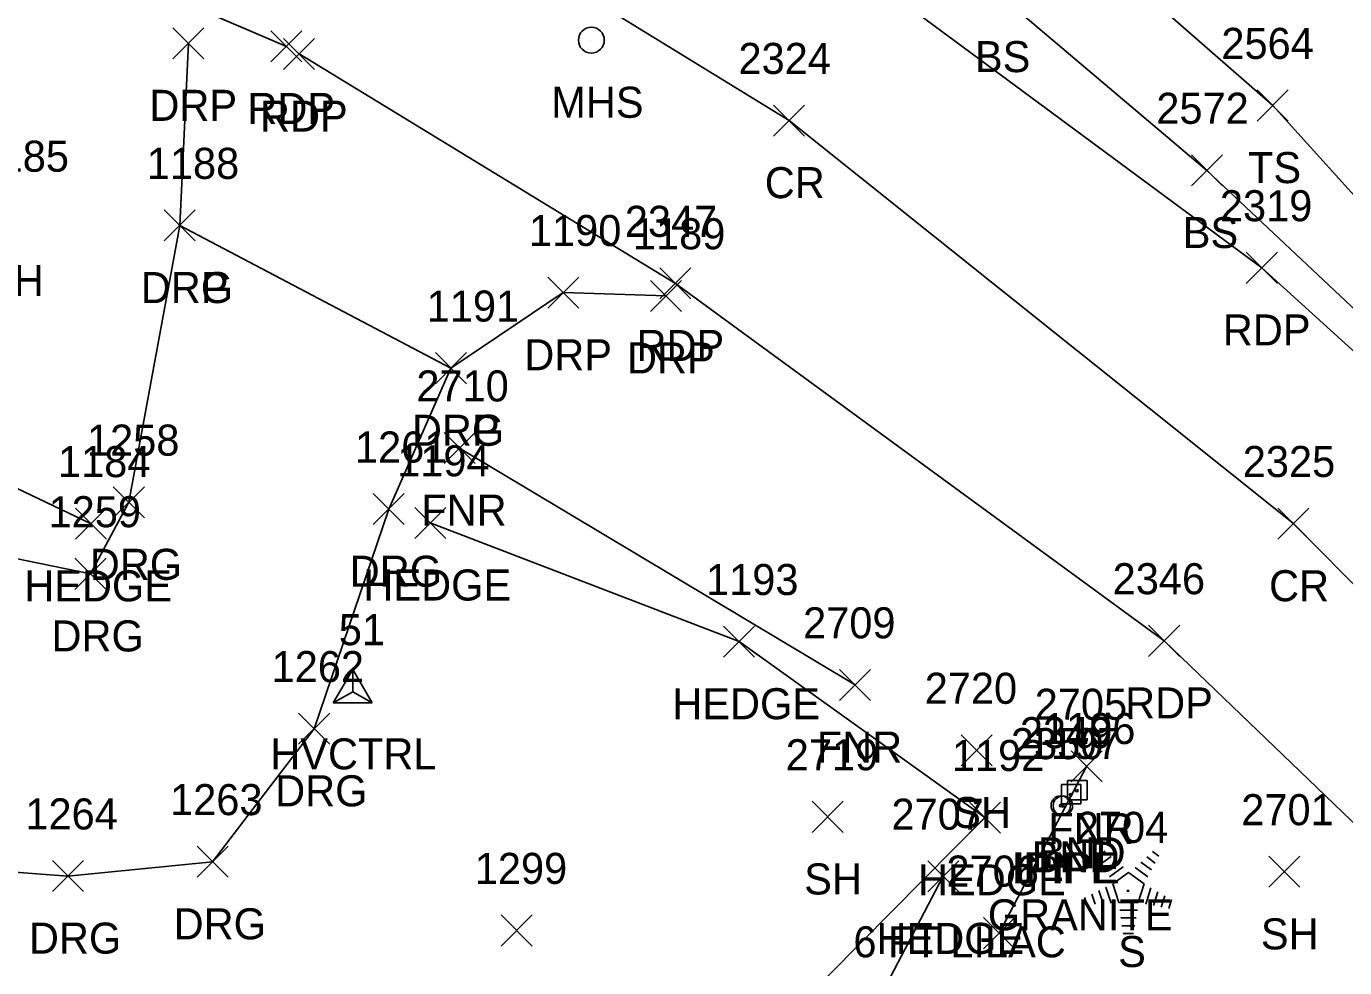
# Model space of a CAD drawing. Extents: x 1638344 to 1639591, y 610835 to 612202.
# Drawn here: x 1638794.9 to 1638879.7, y 611608.8 to 611669.4 of the extents above; entities that cross this region are included whole.
import ezdxf

# ---------------------------------------------------------------- set-up
doc = ezdxf.new("R2010")
doc.units = 0
for name, color, linetype in [('C_A', 7, 'Continuous'), ('C_I', 7, 'Continuous'), ('CPSM', 7, 'Continuous'), ('L_A', 7, 'Continuous'), ('L_C', 7, 'Continuous'), ('L_I', 7, 'Continuous'), ('L_TIC', 7, 'Continuous'), ('LAHR', 7, 'Continuous'), ('LELB', 7, 'Continuous'), ('Level 18', 7, 'Continuous'), ('LFNC', 7, 'Continuous'), ('LTC', 7, 'Continuous'), ('M_A', 7, 'Continuous'), ('M_C', 7, 'Continuous'), ('M_I', 7, 'Continuous'), ('MPIP', 7, 'Continuous'), ('P_A', 7, 'Continuous'), ('P_I', 7, 'Continuous'), ('P_TIC', 7, 'Continuous'), ('PET', 7, 'Continuous'), ('PRC', 7, 'Continuous'), ('R_A', 7, 'Continuous'), ('R_I', 7, 'Continuous'), ('R_TIC', 7, 'Continuous'), ('RDG', 7, 'Continuous'), ('RDP', 7, 'Continuous'), ('U_A', 7, 'Continuous'), ('USMH', 7, 'Continuous')]:
    doc.layers.add(name, color=color, linetype=linetype)

msp = doc.modelspace()

# ---------------------------------------------------------------- linework, layer by layer
at = {"layer": 'CPSM'}
for p, q in [((1638814.637, 611625.834), (1638815.887, 611627.999)), ((1638817.137, 611625.834), (1638815.887, 611627.999)), ((1638815.888, 611626.555), (1638815.887, 611627.999)), ((1638814.637, 611625.834), (1638815.888, 611626.555)), ((1638815.888, 611626.555), (1638815.888, 611626.555)), ((1638815.888, 611626.555), (1638817.137, 611625.834)), ((1638814.637, 611625.834), (1638817.137, 611625.834))]:
    msp.add_line(p, q, dxfattribs=at)
at = {"layer": 'L_TIC'}
for points in [[(1638874.108, 611663.315), (1638876.108, 611665.315)], [(1638876.108, 611663.315), (1638874.108, 611665.315)], [(1638869.873, 611659.135), (1638871.873, 611661.135)], [(1638871.873, 611659.135), (1638869.873, 611661.135)], [(1638821.762, 611641.254), (1638823.762, 611643.254)], [(1638823.762, 611641.254), (1638821.762, 611643.254)], [(1638798.04, 611636.379), (1638800.04, 611638.379)], [(1638800.04, 611636.379), (1638798.04, 611638.379)], [(1638819.874, 611636.431), (1638821.874, 611638.431)], [(1638821.874, 611636.431), (1638819.874, 611638.431)], [(1638839.755, 611628.784), (1638841.755, 611630.784)], [(1638841.755, 611628.784), (1638839.755, 611630.784)], [(1638847.222, 611625.995), (1638849.222, 611627.995)], [(1638849.222, 611625.995), (1638847.222, 611627.995)], [(1638855.05, 611621.779), (1638857.05, 611623.779)], [(1638857.05, 611621.779), (1638855.05, 611623.779)], [(1638862.123, 611620.749), (1638864.123, 611622.749)], [(1638864.123, 611620.749), (1638862.123, 611622.749)], [(1638845.46, 611617.498), (1638847.46, 611619.498)], [(1638847.46, 611617.498), (1638845.46, 611619.498)], [(1638855.577, 611617.45), (1638857.577, 611619.45)], [(1638857.577, 611617.45), (1638855.577, 611619.45)], [(1638855.577, 611617.45), (1638857.577, 611619.45)], [(1638857.577, 611617.45), (1638855.577, 611619.45)], [(1638874.853, 611613.961), (1638876.853, 611615.961)], [(1638876.853, 611613.961), (1638874.853, 611615.961)], [(1638852.901, 611613.669), (1638854.901, 611615.669)], [(1638854.901, 611613.669), (1638852.901, 611615.669)], [(1638825.443, 611610.179), (1638827.443, 611612.179)], [(1638827.443, 611610.179), (1638825.443, 611612.179)], [(1638856.497, 611610.005), (1638858.497, 611612.005)], [(1638858.497, 611610.005), (1638856.497, 611612.005)]]:
    msp.add_lwpolyline(points, dxfattribs=at)
at = {"layer": 'LAHR'}
for points in [[(1638761.697, 611652.078), (1638780.628, 611646.181), (1638799.04, 611637.379)], [(1638856.577, 611618.45), (1638840.755, 611629.784), (1638820.874, 611637.431)], [(1638856.577, 611618.45), (1638840.558, 611602.258), (1638827.804, 611576.732), (1638816.188, 611554.655), (1638804.751, 611532.583)], [(1638853.901, 611614.669), (1638842.923, 611593.705)]]:
    msp.add_lwpolyline(points, dxfattribs=at)
at = {"layer": 'LELB'}
for points in [[(1638873.205, 611711.87), (1638857.7, 611692.044), (1638852.155, 611680.328), (1638857.497, 611671.464), (1638870.873, 611660.135), (1638883.737, 611648.029), (1638891.391, 611642.842)], [(1638893.271, 611644.216), (1638875.108, 611664.315), (1638860.571, 611677.054), (1638859.029, 611684.692), (1638875.948, 611708.59)]]:
    msp.add_lwpolyline(points, dxfattribs=at)
at = {"layer": 'Level 18'}
for p, q in [((1638862.751, 611620.576), (1638861.501, 611620.576)), ((1638861.501, 611620.576), (1638861.501, 611619.326)), ((1638862.751, 611620.576), (1638861.501, 611620.576)), ((1638861.501, 611620.576), (1638861.501, 611619.326)), ((1638863.151, 611620.845), (1638861.901, 611620.845)), ((1638861.901, 611620.845), (1638861.901, 611619.595)), ((1638863.151, 611620.845), (1638861.901, 611620.845)), ((1638861.901, 611620.845), (1638861.901, 611619.595)), ((1638862.751, 611619.326), (1638862.751, 611620.576)), ((1638862.751, 611619.326), (1638862.751, 611620.576)), ((1638863.151, 611619.595), (1638863.151, 611620.845)), ((1638863.151, 611619.595), (1638863.151, 611620.845)), ((1638861.501, 611619.326), (1638862.751, 611619.326)), ((1638861.501, 611619.326), (1638862.751, 611619.326)), ((1638861.901, 611619.595), (1638863.151, 611619.595)), ((1638861.901, 611619.595), (1638863.151, 611619.595))]:
    msp.add_line(p, q, dxfattribs=at)
for centre in [(1638862.501, 611620.183), (1638862.101, 611619.914)]:
    msp.add_circle(centre, 0.0833, dxfattribs=at)
at = {"layer": 'LFNC'}
for points in [[(1638848.222, 611626.995), (1638822.762, 611642.254)], [(1638863.123, 611621.749), (1638857.497, 611611.005)]]:
    msp.add_lwpolyline(points, dxfattribs=at)
at = {"layer": 'LTC'}
for p, q in [((1638863.966, 611616.031), (1638864.321, 611616.289)), ((1638864.176, 611615.566), (1638864.705, 611615.95)), ((1638866.993, 611615.923), (1638867.543, 611615.524)), ((1638867.364, 611616.272), (1638867.784, 611615.967)), ((1638864.385, 611615.1), (1638865.089, 611615.611)), ((1638864.595, 611614.634), (1638865.473, 611615.272)), ((1638866.251, 611615.227), (1638867.061, 611614.638)), ((1638866.622, 611615.575), (1638867.302, 611615.081)), ((1638864.82, 611614.179), (1638865.831, 611614.914)), ((1638864.82, 611614.179), (1638865.207, 611612.986)), ((1638865.831, 611614.914), (1638866.828, 611614.189)), ((1638866.828, 611614.189), (1638866.437, 611612.986)), ((1638862.999, 611613.31), (1638863.151, 611612.842)), ((1638863.454, 611613.527), (1638863.666, 611612.875)), ((1638863.91, 611613.744), (1638864.181, 611612.908)), ((1638864.365, 611613.96), (1638864.696, 611612.941)), ((1638867.266, 611613.918), (1638866.928, 611612.878)), ((1638867.71, 611613.667), (1638867.423, 611612.783)), ((1638868.155, 611613.417), (1638867.918, 611612.688)), ((1638866.437, 611612.986), (1638865.207, 611612.986)), ((1638866.399, 611612.486), (1638865.254, 611612.486)), ((1638868.599, 611613.167), (1638868.412, 611612.593)), ((1638866.315, 611611.986), (1638865.327, 611611.986)), ((1638866.231, 611611.486), (1638865.4, 611611.486)), ((1638866.147, 611610.986), (1638865.472, 611610.986))]:
    msp.add_line(p, q, dxfattribs=at)
at = {"layer": 'MPIP'}
for centre, radius in [((1638861.462, 611619.223), 0.625), ((1638861.598, 611619.213), 0.625), ((1638861.462, 611619.223), 0.0833), ((1638861.598, 611619.213), 0.0833)]:
    msp.add_circle(centre, radius, dxfattribs=at)
at = {"layer": 'P_TIC'}
for points in [[(1638810.617, 611667.124), (1638812.617, 611669.124)], [(1638812.617, 611667.124), (1638810.617, 611669.124)], [(1638811.431, 611666.635), (1638813.431, 611668.635)], [(1638813.431, 611666.635), (1638811.431, 611668.635)], [(1638842.976, 611662.347), (1638844.976, 611664.347)], [(1638844.976, 611662.347), (1638842.976, 611664.347)], [(1638873.406, 611652.859), (1638875.406, 611654.859)], [(1638875.406, 611652.859), (1638873.406, 611654.859)], [(1638835.66, 611651.855), (1638837.66, 611653.855)], [(1638837.66, 611651.855), (1638835.66, 611653.855)], [(1638875.437, 611636.386), (1638877.437, 611638.386)], [(1638877.437, 611636.386), (1638875.437, 611638.386)], [(1638867.117, 611628.836), (1638869.117, 611630.836)], [(1638869.117, 611628.836), (1638867.117, 611630.836)]]:
    msp.add_lwpolyline(points, dxfattribs=at)
at = {"layer": 'PET'}
for points in [[(1638811.617, 611668.124), (1638782.382, 611680.66), (1638760.269, 611687.763), (1638749.075, 611690.276), (1638736.887, 611691.427), (1638737.261, 611703.383), (1638737.238, 611715.506), (1638749.613, 611712.202), (1638777.651, 611708.363), (1638798.655, 611701.427), (1638823.202, 611689.416)], [(1639148.644, 611331.084), (1639142.07, 611329.181), (1639135.695, 611328.741), (1639125.685, 611331.146), (1639119.176, 611334.876), (1639114.186, 611340.569), (1639098.763, 611361.782), (1639080.318, 611387.337), (1639061.62, 611413.479), (1639039.15, 611444.22), (1639014.337, 611480.362), (1638988.412, 611516.904), (1638963.389, 611551.848), (1638935.462, 611588.701), (1638918.51, 611609.364), (1638899.727, 611630.857), (1638874.406, 611653.859), (1638846.552, 611674.469), (1638833.143, 611682.537), (1638823.865, 611689.161)], [(1639117.365, 611283.377), (1639114.123, 611301.894), (1639095.515, 611328.502), (1639070.515, 611363.262), (1639041.381, 611404.693), (1639011.578, 611446.402), (1638984.33, 611485.148), (1638954.173, 611527.497), (1638934.327, 611554.774), (1638918.881, 611575.585), (1638893.271, 611605.667), (1638868.117, 611629.836), (1638836.66, 611652.855), (1638812.431, 611667.635)]]:
    msp.add_lwpolyline(points, dxfattribs=at)
at = {"layer": 'PRC'}
msp.add_lwpolyline([(1638818.793, 611678.836), (1638843.976, 611663.347), (1638876.437, 611637.386), (1638906.243, 611607.195), (1638934.14, 611573.691), (1638965.308, 611531.428), (1638998.822, 611484.341), (1639033.825, 611434.483), (1639068.011, 611386.3), (1639093.943, 611350.49), (1639111.892, 611325.375), (1639129.228, 611302.77)], dxfattribs=at)
at = {"layer": 'R_TIC'}
for points in [[(1638804.311, 611667.326), (1638806.311, 611669.326)], [(1638806.311, 611667.326), (1638804.311, 611669.326)], [(1638803.754, 611655.589), (1638805.754, 611657.589)], [(1638805.754, 611655.589), (1638803.754, 611657.589)], [(1638803.754, 611655.589), (1638805.754, 611657.589)], [(1638805.754, 611655.589), (1638803.754, 611657.589)], [(1638828.44, 611651.263), (1638830.44, 611653.263)], [(1638830.44, 611651.263), (1638828.44, 611653.263)], [(1638835.055, 611651.054), (1638837.055, 611653.054)], [(1638837.055, 611651.054), (1638835.055, 611653.054)], [(1638821.207, 611646.398), (1638823.207, 611648.398)], [(1638823.207, 611646.398), (1638821.207, 611648.398)], [(1638821.207, 611646.398), (1638823.207, 611648.398)], [(1638823.207, 611646.398), (1638821.207, 611648.398)], [(1638821.207, 611646.398), (1638823.207, 611648.398)], [(1638823.207, 611646.398), (1638821.207, 611648.398)], [(1638800.474, 611637.763), (1638802.474, 611639.763)], [(1638802.474, 611637.763), (1638800.474, 611639.763)], [(1638817.203, 611637.318), (1638819.203, 611639.318)], [(1638819.203, 611637.318), (1638817.203, 611639.318)], [(1638798.009, 611633.152), (1638800.009, 611635.152)], [(1638800.009, 611633.152), (1638798.009, 611635.152)], [(1638812.404, 611623.175), (1638814.404, 611625.175)], [(1638814.404, 611623.175), (1638812.404, 611625.175)], [(1638805.87, 611614.608), (1638807.87, 611616.608)], [(1638807.87, 611614.608), (1638805.87, 611616.608)], [(1638796.555, 611613.687), (1638798.555, 611615.687)], [(1638798.555, 611613.687), (1638796.555, 611615.687)]]:
    msp.add_lwpolyline(points, dxfattribs=at)
at = {"layer": 'RDG'}
for points in [[(1638804.754, 611656.589), (1638801.474, 611638.763), (1638799.009, 611634.152), (1638786.873, 611636.64), (1638769.768, 611642.842)], [(1638822.207, 611647.398), (1638818.203, 611638.318), (1638813.404, 611624.175), (1638806.87, 611615.608), (1638797.555, 611614.687), (1638788.459, 611615.375), (1638771.793, 611619.289), (1638763.161, 611621.314), (1638769.768, 611642.842)]]:
    msp.add_lwpolyline(points, dxfattribs=at)
at = {"layer": 'RDP'}
for points in [[(1638805.311, 611668.326), (1638804.754, 611656.589), (1638822.207, 611647.398)], [(1638836.055, 611652.054), (1638829.44, 611652.263), (1638822.207, 611647.398)]]:
    msp.add_lwpolyline(points, dxfattribs=at)
at = {"layer": 'USMH'}
for p, q in [((1638831.247, 611668.524), (1638831.247, 611668.524)), ((1638832.08, 611668.524), (1638832.08, 611668.524))]:
    msp.add_line(p, q, dxfattribs=at)
msp.add_circle((1638831.247, 611668.524), 0.833, dxfattribs=at)

# ---------------------------------------------------------------- texts
at = {"layer": 'C_A'}
msp.add_text('HVCTRL', height=2, dxfattribs=at).set_placement((1638810.58, 611621.555))
at = {"layer": 'C_I'}
msp.add_text('51', height=2, dxfattribs=at).set_placement((1638814.99, 611629.555))
at = {"layer": 'L_A'}
for s, p in [('BS', (1638855.938, 611666.464)), ('TS', (1638873.517, 611659.315)), ('BS', (1638869.314, 611655.135)), ('SH', (1638792.285, 611652.051)), ('FNR', (1638820.297, 611637.254)), ('HEDGE', (1638794.741, 611632.379)), ('HEDGE', (1638816.574, 611632.431)), ('HEDGE', (1638836.456, 611624.784)), ('FNR', (1638845.757, 611621.995)), ('SH', (1638854.538, 611617.779)), ('FNR', (1638860.658, 611616.749)), ('SH', (1638844.948, 611613.498)), ('HEDGE', (1638852.277, 611613.45)), ('HEDGE', (1638852.277, 611613.45)), ('HEDGE', (1638849.602, 611609.669)), ('SH', (1638874.341, 611609.961)), ('S', (1638865.157, 611608.823))]:
    msp.add_text(s, height=2, dxfattribs=at).set_placement(p)
at = {"layer": 'L_C'}
msp.add_text('6 FT LILAC', height=2, dxfattribs=at).set_placement((1638848.112, 611609.45))
msp.add_text('6 FT LILAC', height=2, dxfattribs=at).set_placement((1638848.112, 611609.45))
at = {"layer": 'L_I'}
for s, p in [('2564', (1638871.801, 611667.315)), ('2572', (1638867.613, 611663.135)), ('1185', (1638791.671, 611660.051)), ('2710', (1638819.982, 611645.254)), ('1184', (1638796.914, 611640.379)), ('1194', (1638818.748, 611640.431)), ('1193', (1638838.629, 611632.784)), ('2709', (1638844.876, 611629.995)), ('2720', (1638852.704, 611625.779)), ('2705', (1638859.784, 611624.749)), ('2719', (1638843.759, 611621.498)), ('1192', (1638854.451, 611621.45)), ('1192', (1638854.451, 611621.45)), ('2707', (1638850.562, 611617.669)), ('2701', (1638873.081, 611617.961)), ('2704', (1638862.432, 611616.823)), ('1299', (1638823.742, 611614.179)), ('2706', (1638854.103, 611614.005))]:
    msp.add_text(s, height=2, dxfattribs=at).set_placement(p)
at = {"layer": 'LTC'}
msp.add_text('.', height=1.037, rotation=270, dxfattribs=at).set_placement((1638865.714, 611613.927))
at = {"layer": 'M_A'}
for s, p in [('BND', (1638859.588, 611614.919)), ('BND', (1638859.988, 611615.188)), ('IPIPE', (1638858.297, 611614.223)), ('IPIPE', (1638858.433, 611614.213))]:
    msp.add_text(s, height=2, dxfattribs=at).set_placement(p)
at = {"layer": 'M_C'}
msp.add_text('GRANITE', height=2, dxfattribs=at).set_placement((1638856.768, 611611.188))
at = {"layer": 'M_I'}
for s, p in [('1196', (1638860.319, 611623.188)), ('2349', (1638858.832, 611622.919)), ('2350', (1638858.252, 611622.213)), ('1197', (1638859.336, 611622.223))]:
    msp.add_text(s, height=2, dxfattribs=at).set_placement(p)
at = {"layer": 'P_A'}
for s, p in [('RDP', (1638809.105, 611663.124)), ('RDP', (1638809.919, 611662.635)), ('CR', (1638842.409, 611658.347)), ('RDP', (1638871.894, 611648.859)), ('RDP', (1638834.148, 611647.855)), ('CR', (1638874.87, 611632.386)), ('RDP', (1638865.605, 611624.836))]:
    msp.add_text(s, height=2, dxfattribs=at).set_placement(p)
at = {"layer": 'P_I'}
for s, p in [('2324', (1638840.716, 611666.347)), ('2319', (1638871.705, 611656.859)), ('2347', (1638833.4, 611655.855)), ('2325', (1638873.177, 611640.386)), ('2346', (1638864.802, 611632.836))]:
    msp.add_text(s, height=2, dxfattribs=at).set_placement(p)
at = {"layer": 'R_A'}
for s, p in [('DRP', (1638802.799, 611663.326)), ('DRG', (1638802.243, 611651.589)), ('DRP', (1638802.243, 611651.589)), ('DRP', (1638826.928, 611647.263)), ('DRP', (1638833.544, 611647.054)), ('DRG', (1638819.696, 611642.398)), ('DRP', (1638819.696, 611642.398)), ('DRP', (1638819.696, 611642.398)), ('DRG', (1638798.962, 611633.763)), ('DRG', (1638815.692, 611633.318)), ('DRG', (1638796.497, 611629.152)), ('DRG', (1638810.892, 611619.175)), ('DRG', (1638804.358, 611610.608)), ('DRG', (1638795.043, 611609.687))]:
    msp.add_text(s, height=2, dxfattribs=at).set_placement(p)
at = {"layer": 'R_I'}
for s, p in [('1188', (1638802.628, 611659.589)), ('1188', (1638802.628, 611659.589)), ('1190', (1638827.228, 611655.263)), ('1189', (1638833.922, 611655.054)), ('1191', (1638820.648, 611650.398)), ('1191', (1638820.648, 611650.398)), ('1191', (1638820.648, 611650.398)), ('1258', (1638798.781, 611641.763)), ('1261', (1638816.03, 611641.318)), ('1259', (1638796.308, 611637.152)), ('1262', (1638810.664, 611627.175)), ('1263', (1638804.13, 611618.608)), ('1264', (1638794.815, 611617.687))]:
    msp.add_text(s, height=2, dxfattribs=at).set_placement(p)
at = {"layer": 'U_A'}
msp.add_text('MHS', height=2, dxfattribs=at).set_placement((1638828.664, 611663.524))

doc.saveas('drawing.dxf')
